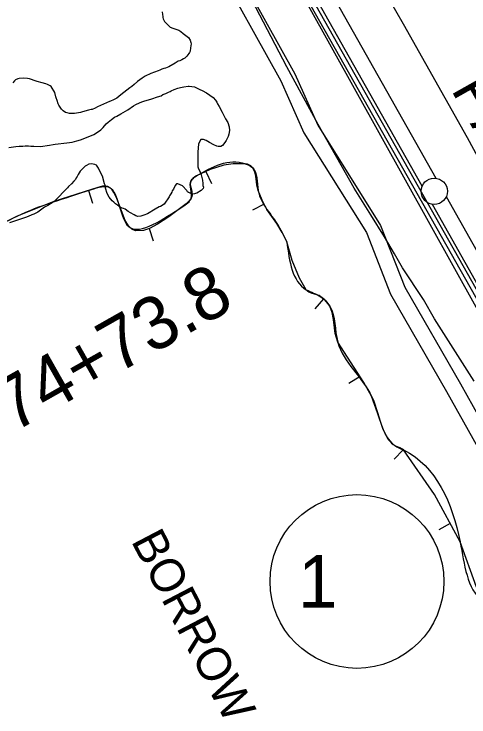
# Model space of a CAD drawing. Extents: x 3177185 to 3215018, y 812988 to 838321.
# Drawn here: x 3194496 to 3195360, y 819225 to 820560 of the extents above; entities that cross this region are included whole.
import ezdxf

# ---------------------------------------------------------------- set-up
doc = ezdxf.new("R2010")
doc.units = 0
for name, color, linetype in [('V-BORW-IDEN', 7, 'Continuous'), ('V-BORW-LINE', 7, 'Continuous'), ('V-LEVE-TOET', 7, 'Continuous'), ('V-RAIL-IDEN', 7, 'Continuous'), ('V-RAIL-TRAK', 7, 'Continuous'), ('V-ROAD-CNTR', 7, 'Continuous'), ('V-ROAD-IDEN', 7, 'Continuous'), ('V-SITE-VEGE', 7, 'Continuous'), ('V-SURV-IDEN', 7, 'Continuous'), ('V-SURV-LINE', 7, 'Continuous'), ('V-TOPO-SHOR', 7, 'Continuous')]:
    doc.layers.add(name, color=color, linetype=linetype)

msp = doc.modelspace()

# ---------------------------------------------------------------- linework, layer by layer
at = {"layer": 'V-BORW-LINE'}
for p, q in [((3194860.5, 820261), (3194871.3, 820238.4)), ((3194638, 820224.9), (3194645.6, 820201)), ((3194971.4, 820199.1), (3194949.2, 820187.8)), ((3194752.8, 820152.8), (3194760.8, 820129.1)), ((3195083.7, 820019.3), (3195067.6, 820000.2)), ((3195153.2, 819871.8), (3195132.2, 819858.2)), ((3195235.4, 819732.7), (3195218.3, 819714.5)), ((3195324.6, 819592.3), (3195302.5, 819580.5))]:
    msp.add_line(p, q, dxfattribs=at)
for points in [[(3195014.2, 820127.7), (3195005.1, 820145.4), (3194995.1, 820162.4), (3194985.8, 820175.7), (3194976.6, 820189), (3194967.6, 820206.7), (3194960, 820224.8), (3194957.2, 820235.5), (3194955.3, 820252.1), (3194953.2, 820260.4), (3194949, 820268.4), (3194946.1, 820271.5), (3194943.6, 820273.3), (3194939.5, 820275), (3194935.3, 820275.8), (3194912.4, 820275.7), (3194894.9, 820273), (3194868.7, 820264.9), (3194842.9, 820252.6), (3194839.8, 820250.7), (3194835.9, 820247.5), (3194832.6, 820243.6), (3194831.1, 820239.8), (3194830.8, 820236.2), (3194833.7, 820222.8), (3194834.5, 820216.3), (3194834.1, 820213.3), (3194832.8, 820210.5), (3194829.2, 820205.8), (3194822.9, 820199.6), (3194815.7, 820194), (3194790.2, 820175), (3194769, 820161), (3194753.3, 820153), (3194742.1, 820149.2), (3194726.9, 820148.6), (3194720.3, 820151.2), (3194714.7, 820155.9), (3194707.3, 820167.7), (3194691.3, 820209.9), (3194686.1, 820220.8), (3194682.9, 820225.9), (3194678.6, 820230.1), (3194674.6, 820232.2), (3194670.9, 820233.1), (3194664, 820233), (3194653.5, 820230.2), (3194643.3, 820226.6), (3194572.1, 820203.9), (3194502.5, 820176.3), (3194474.3, 820162.1)], [(3195051.2, 820036.5), (3195038.2, 820058.1), (3195024.1, 820092.2), (3195014.2, 820127.7)], [(3195374.2, 819471.5), (3195343.1, 819557.8), (3195294.7, 819647.9), (3195236, 819732.1), (3195234, 819733.9), (3195229.7, 819736.2), (3195222.6, 819738.7), (3195219.2, 819740.3), (3195216.4, 819742.6), (3195205.6, 819756), (3195201, 819763.3), (3195197, 819771), (3195186.1, 819802.7), (3195175.2, 819834.1), (3195160.5, 819860.5), (3195110.9, 819937.1), (3195105.8, 819953.5), (3195102.9, 819980), (3195100.5, 819993.1), (3195095.7, 820005.5), (3195092.3, 820010.6), (3195086.1, 820017.2), (3195079.1, 820023.1), (3195075.8, 820025.2), (3195062.5, 820029.5), (3195056.2, 820032), (3195053.5, 820033.9), (3195051.2, 820036.5)]]:
    msp.add_lwpolyline(points, dxfattribs=at)
for points in [[(3194584.7, 819145.8), (3194447.3, 819133.8), (3194404.6, 819199.8), (3194370.1, 819313.4), (3194215, 819487.3), (3194145.9, 819581.9), (3194097.2, 819676.7), (3194042.5, 819943.4), (3194160.3, 819974.7), (3194208.8, 820009.4), (3194249.9, 820024.5), (3194281, 820046.5), (3194446.7, 820147), (3194502.5, 820176.3), (3194643.3, 820226.6), (3194678.6, 820230.1), (3194691.3, 820209.9), (3194714.7, 820155.9), (3194815.7, 820194), (3194832.8, 820210.5), (3194832.6, 820243.6), (3194842.9, 820252.6), (3194935.3, 820275.8), (3194949, 820268.4), (3194960, 820224.8), (3194976.6, 820189), (3194995.1, 820162.4), (3195014.2, 820127.7)], [(3195014.2, 820127.7), (3195051.2, 820036.5), (3195079.1, 820023.1), (3195095.7, 820005.5), (3195110.9, 819937.1), (3195175.2, 819834.1), (3195197, 819771), (3195216.4, 819742.6), (3195236, 819732.1), (3195343.1, 819557.8), (3195386.4, 819443.9), (3195423.7, 819413.9), (3195435.2, 819377.3), (3195508.3, 819247.2), (3195522.8, 819188.1), (3195531.4, 819165.4), (3195561.3, 819137), (3195612, 819024.1), (3195671.6, 818940.9), (3195804.7, 818724.1), (3195856.6, 818587.8), (3195891.3, 818540.3), (3195947, 818433), (3195956.5, 818375.3), (3195958.6, 818365.3)]]:
    msp.add_spline(points, degree=3, dxfattribs=at)
at = {"layer": 'V-LEVE-TOET'}
for points in [[(3195369.9, 819862.9), (3195294.5, 819981.2), (3195273.4, 820017.6), (3195233.7, 820077.8), (3195218.6, 820104.8), (3195199.4, 820136.6), (3195173.6, 820178.4), (3195142.1, 820229.4), (3195073.8, 820350.4), (3195014.1, 820460), (3194933, 820615.4), (3194826.9, 820807.9), (3194726, 820985.8), (3194603, 821208.6), (3194474, 821433.9), (3194336.7, 821672), (3194255.3, 821803.4)], [(3195368.6, 820787.1), (3195357.2, 820770.6), (3195346.6, 820754.6), (3195334.3, 820739.9), (3195319.5, 820726.5), (3195306.2, 820715.4), (3195290.9, 820704.8), (3195270.3, 820693.3), (3195230.7, 820666.8), (3195213.6, 820660.8), (3195195.1, 820654), (3195186.1, 820650.5), (3195181.3, 820645.8), (3195179.2, 820635.1), (3195181.5, 820629), (3195191.4, 820611.7), (3195205.7, 820592.5), (3195235, 820541.5), (3195356.3, 820325.5), (3195489.6, 820080.5)]]:
    msp.add_lwpolyline(points, dxfattribs=at)
at = {"layer": 'V-RAIL-TRAK'}
msp.add_lwpolyline([(3194238.4, 822033.7), (3194389.3, 821767.4), (3194710.7, 821197.3), (3195003.1, 820677), (3195353.4, 820056.4), (3195586, 819645), (3195933.8, 819028.7), (3196235.6, 818491.2), (3196308.1, 818364.4)], dxfattribs=at)
at = {"layer": 'V-ROAD-CNTR'}
for points in [[(3193546.7, 823116.4), (3193719.6, 822803.7), (3193783.2, 822690.8), (3193839.5, 822561.1), (3193931.2, 822385.2), (3194075.1, 822116.1), (3194127.2, 822033.7), (3194185.2, 821977.8), (3194639.7, 821147.1), (3195029.5, 820446.4), (3195072.9, 820348.7), (3195192.1, 820158.7), (3195238.4, 820041.1), (3195343.7, 819857.8), (3195584.5, 819427.5), (3195690.6, 819249.8), (3195813.3, 819032.3), (3196001.4, 818698.6), (3196174.6, 818374.5)], [(3193520.4, 823101.8), (3193693.4, 822789.1), (3193756.3, 822677.4), (3193812.4, 822548.2), (3193904.7, 822371.2), (3194049.2, 822101), (3194103.8, 822014.6), (3194161.1, 821959.4), (3194613.5, 821132.6), (3195002.6, 820433), (3195046.3, 820334.6), (3195165.2, 820145.1), (3195211.3, 820028), (3195317.6, 819843), (3195558.5, 819412.5), (3195664.6, 819234.7), (3195787.2, 819017.6), (3195975.1, 818684.1), (3196148.1, 818360.4)], [(3193654.2, 823085.5), (3194393.6, 821781.9), (3194932.5, 820818.5), (3195643.8, 819559.4), (3196039.6, 818863.6), (3196103.7, 818747.1), (3196200.1, 818577.4), (3196283.3, 818430.9), (3196319.7, 818367.1)]]:
    msp.add_lwpolyline(points, dxfattribs=at)
at = {"layer": 'V-ROAD-IDEN'}
msp.add_circle((3195147.4, 819482.4), 165, dxfattribs=at)
at = {"layer": 'V-SITE-VEGE'}
for p, q in [((3194777.6, 820564.2), (3194778.5, 820559.3)), ((3194778.5, 820559.3), (3194778.9, 820555.3)), ((3194778.9, 820555.3), (3194778.9, 820553.3)), ((3194778.9, 820553.3), (3194779.4, 820550.9)), ((3194779.4, 820550.9), (3194781.8, 820545.6)), ((3194781.8, 820545.6), (3194792.9, 820534.8)), ((3194792.9, 820534.8), (3194798.1, 820532.9)), ((3194798.1, 820532.9), (3194801.8, 820532.1)), ((3194801.8, 820532.1), (3194809.1, 820529.3)), ((3194809.1, 820529.3), (3194813.1, 820526.9)), ((3194813.1, 820526.9), (3194817.2, 820523.3)), ((3194817.2, 820523.3), (3194827.4, 820515.7)), ((3194827.4, 820515.7), (3194830.7, 820510.5)), ((3194830.7, 820510.5), (3194832.3, 820506.1)), ((3194832.4, 820503.7), (3194831.6, 820495.6)), ((3194832.3, 820506.1), (3194832.4, 820503.7)), ((3194829.7, 820486.7), (3194828.1, 820485)), ((3194830.5, 820489.5), (3194829.7, 820486.7)), ((3194831.6, 820495.6), (3194830.5, 820489.5)), ((3194814.9, 820473.2), (3194811.2, 820471.1)), ((3194818.1, 820474.8), (3194814.9, 820473.2)), ((3194820.9, 820476.5), (3194818.1, 820474.8)), ((3194824.1, 820479.7), (3194820.9, 820476.5)), ((3194828.1, 820485), (3194824.1, 820479.7)), ((3194790.3, 820460), (3194783.9, 820457.1)), ((3194802.4, 820467), (3194790.3, 820460)), ((3194808, 820470.3), (3194802.4, 820467)), ((3194811.2, 820471.1), (3194808, 820470.3)), ((3194756.1, 820447.2), (3194745.6, 820442.2)), ((3194769.8, 820452.1), (3194756.1, 820447.2)), ((3194773.4, 820453.4), (3194769.8, 820452.1)), ((3194777, 820455), (3194773.4, 820453.4)), ((3194780.7, 820456.3), (3194777, 820455)), ((3194783.9, 820457.1), (3194780.7, 820456.3)), ((3194497.5, 820433), (3194493.9, 820429.3)), ((3194499.1, 820435), (3194497.5, 820433)), ((3194503.5, 820437.1), (3194499.1, 820435)), ((3194506.3, 820437.9), (3194503.5, 820437.1)), ((3194514, 820438), (3194506.3, 820437.9)), ((3194522.1, 820437.7), (3194514, 820438)), ((3194525.8, 820436.9), (3194522.1, 820437.7)), ((3194529.8, 820435.7), (3194525.8, 820436.9)), ((3194534.3, 820434.1), (3194529.8, 820435.7)), ((3194540.4, 820431.8), (3194534.3, 820434.1)), ((3194739.6, 820438.5), (3194730.8, 820432)), ((3194745.6, 820442.2), (3194739.6, 820438.5)), ((3194549.7, 820429.4), (3194540.4, 820431.8)), ((3194556.6, 820427.5), (3194549.7, 820429.4)), ((3194560.2, 820426.3), (3194556.6, 820427.5)), ((3194565.1, 820423.9), (3194560.2, 820426.3)), ((3194566.7, 820422.7), (3194565.1, 820423.9)), ((3194573.7, 820411.1), (3194566.7, 820422.7)), ((3194716.3, 820420.1), (3194699.1, 820406.6)), ((3194719.9, 820422.6), (3194716.3, 820420.1)), ((3194724.3, 820426.2), (3194719.9, 820422.6)), ((3194730.8, 820432), (3194724.3, 820426.2)), ((3194800.4, 820416.9), (3194807.3, 820419.3)), ((3194807.3, 820419.3), (3194812.5, 820420.6)), ((3194812.5, 820420.6), (3194818.6, 820421.9)), ((3194818.6, 820421.9), (3194827.1, 820422.8)), ((3194827.1, 820422.8), (3194829.1, 820423.2)), ((3194829.1, 820423.2), (3194838.8, 820421.7)), ((3194838.8, 820421.7), (3194849.4, 820416.9)), ((3194575.8, 820402.6), (3194573.7, 820411.1)), ((3194699.1, 820406.6), (3194691.4, 820400.5)), ((3194775.5, 820404.9), (3194778.7, 820406.9)), ((3194778.7, 820406.9), (3194784.3, 820409)), ((3194784.3, 820409), (3194789.6, 820411.5)), ((3194789.6, 820411.5), (3194792.8, 820413.1)), ((3194792.8, 820413.1), (3194794.8, 820414)), ((3194794.8, 820414), (3194800.4, 820416.9)), ((3194849.4, 820416.9), (3194853.8, 820414.9)), ((3194853.8, 820414.9), (3194861.9, 820410.6)), ((3194861.9, 820410.6), (3194874.2, 820401.4)), ((3194576.2, 820400.6), (3194575.8, 820402.6)), ((3194578.3, 820395.8), (3194576.2, 820400.6)), ((3194580.4, 820389.7), (3194578.3, 820395.8)), ((3194677.8, 820393.9), (3194666.1, 820388.9)), ((3194679.8, 820394.3), (3194677.8, 820393.9)), ((3194685.4, 820396.8), (3194679.8, 820394.3)), ((3194691.4, 820400.5), (3194685.4, 820396.8)), ((3194734.8, 820391.6), (3194738.8, 820393.2)), ((3194738.8, 820393.2), (3194742.8, 820394.5)), ((3194742.8, 820394.5), (3194757.8, 820398.7)), ((3194757.8, 820398.7), (3194768.6, 820402.8)), ((3194768.6, 820402.8), (3194775.5, 820404.9)), ((3194874.2, 820401.4), (3194879.1, 820396.2)), ((3194879.1, 820396.2), (3194881.1, 820392.6)), ((3194881.1, 820392.6), (3194882.4, 820389.3)), ((3194581.2, 820386.9), (3194580.4, 820389.7)), ((3194586.5, 820379.3), (3194581.2, 820386.9)), ((3194589.4, 820376.5), (3194586.5, 820379.3)), ((3194650.4, 820381.1), (3194644.8, 820378.6)), ((3194654.8, 820383.5), (3194650.4, 820381.1)), ((3194666.1, 820388.9), (3194654.8, 820383.5)), ((3194712.3, 820378), (3194723.1, 820385.4)), ((3194723.1, 820385.4), (3194727.9, 820387.9)), ((3194727.9, 820387.9), (3194734.8, 820391.6)), ((3194882.4, 820389.3), (3194886, 820384.5)), ((3194886, 820384.5), (3194891.4, 820373.6)), ((3194594.3, 820373.3), (3194589.4, 820376.5)), ((3194597.1, 820372.1), (3194594.3, 820373.3)), ((3194601.6, 820371.3), (3194597.1, 820372.1)), ((3194610.9, 820371.4), (3194601.6, 820371.3)), ((3194622.6, 820373.1), (3194610.9, 820371.4)), ((3194626.6, 820374.4), (3194622.6, 820373.1)), ((3194637.9, 820377.3), (3194626.6, 820374.4)), ((3194642.7, 820378.6), (3194637.9, 820377.3)), ((3194644.8, 820378.6), (3194642.7, 820378.6)), ((3194687.3, 820364), (3194691.8, 820366.1)), ((3194691.8, 820366.1), (3194699, 820370.2)), ((3194699, 820370.2), (3194712.3, 820378)), ((3194891.4, 820373.6), (3194898, 820361.2)), ((3194671.3, 820351.4), (3194674.9, 820354.6)), ((3194674.9, 820354.6), (3194681.7, 820359.9)), ((3194681.7, 820359.9), (3194687.3, 820364)), ((3194898, 820361.2), (3194902.1, 820354.3)), ((3194902.1, 820354.3), (3194905, 820345.9)), ((3194656.9, 820337.1), (3194660.9, 820339.9)), ((3194660.9, 820339.9), (3194665.7, 820344.4)), ((3194665.7, 820344.4), (3194671.3, 820351.4)), ((3194905.1, 820339), (3194904.3, 820332.1)), ((3194905, 820345.9), (3194905.1, 820339)), ((3194630.7, 820324.3), (3194647.6, 820331.3)), ((3194647.6, 820331.3), (3194656.9, 820337.1)), ((3194902.8, 820327.7), (3194899.2, 820320)), ((3194904.3, 820332.1), (3194902.8, 820327.7)), ((3194563.7, 820310.7), (3194570.6, 820312)), ((3194570.6, 820312), (3194574.2, 820312.8)), ((3194574.2, 820312.8), (3194596.8, 820315.1)), ((3194596.8, 820315.1), (3194606.5, 820316.8)), ((3194606.5, 820316.8), (3194615.8, 820319.3)), ((3194615.8, 820319.3), (3194622.3, 820321.4)), ((3194622.3, 820321.4), (3194630.7, 820324.3)), ((3194846.7, 820313.8), (3194845.2, 820297.6)), ((3194850.7, 820321.9), (3194846.7, 820313.8)), ((3194856.3, 820322), (3194850.7, 820321.9)), ((3194861.2, 820320), (3194856.3, 820322)), ((3194867.3, 820316), (3194861.2, 820320)), ((3194875.8, 820311.6), (3194867.3, 820316)), ((3194896.8, 820315.9), (3194892.4, 820310.6)), ((3194899.2, 820320), (3194896.8, 820315.9)), ((3194486.2, 820306.3), (3194499.5, 820308.5)), ((3194499.5, 820308.5), (3194506.3, 820309)), ((3194506.3, 820309), (3194513.2, 820309)), ((3194513.2, 820309), (3194517.7, 820309.5)), ((3194517.7, 820309.5), (3194523.7, 820309.5)), ((3194523.7, 820309.5), (3194528.2, 820308.8)), ((3194528.2, 820308.8), (3194533.8, 820308.8)), ((3194533.8, 820308.8), (3194546.8, 820308.5)), ((3194546.8, 820308.5), (3194563.7, 820310.7)), ((3194881.1, 820309.3), (3194875.8, 820311.6)), ((3194883.9, 820308.5), (3194881.1, 820309.3)), ((3194889.2, 820308.5), (3194883.9, 820308.5)), ((3194892.4, 820310.6), (3194889.2, 820308.5)), ((3194845.2, 820297.6), (3194845.4, 820281.8)), ((3194634, 820272.6), (3194631.6, 820270.9)), ((3194638.1, 820274.6), (3194634, 820272.6)), ((3194643.3, 820275.5), (3194638.1, 820274.6)), ((3194649.8, 820274.3), (3194643.3, 820275.5)), ((3194653, 820272.8), (3194649.8, 820274.3)), ((3194656.7, 820267.5), (3194653, 820272.8)), ((3194845.4, 820281.8), (3194845, 820279.4)), ((3194845, 820279.4), (3194845.5, 820269.7)), ((3194622, 820261.5), (3194618, 820255.4)), ((3194627.2, 820266.9), (3194622, 820261.5)), ((3194629.2, 820268.9), (3194627.2, 820266.9)), ((3194631.6, 820270.9), (3194629.2, 820268.9)), ((3194658.8, 820262.7), (3194656.7, 820267.5)), ((3194664.1, 820252.2), (3194658.8, 820262.7)), ((3194845.5, 820269.7), (3194846.3, 820266.1)), ((3194846.3, 820266.1), (3194848.8, 820261.3)), ((3194848.8, 820261.3), (3194851.7, 820254.4)), ((3194612.9, 820246.1), (3194610.1, 820242.8)), ((3194614.4, 820248.9), (3194612.9, 820246.1)), ((3194616, 820251.4), (3194614.4, 820248.9)), ((3194618, 820255.4), (3194616, 820251.4)), ((3194667.9, 820237.7), (3194664.1, 820252.2)), ((3194851.7, 820254.4), (3194854.2, 820244.7)), ((3194599.6, 820232.2), (3194597.7, 820229.8)), ((3194605.3, 820237.5), (3194599.6, 820232.2)), ((3194610.1, 820242.8), (3194605.3, 820237.5)), ((3194669.2, 820234.9), (3194667.9, 820237.7)), ((3194670, 820229.3), (3194669.2, 820234.9)), ((3194802.2, 820234.5), (3194799, 820227.6)), ((3194804.6, 820237.4), (3194802.2, 820234.5)), ((3194807.4, 820237.4), (3194804.6, 820237.4)), ((3194815.9, 820233.5), (3194807.4, 820237.4)), ((3194824.1, 820225.1), (3194815.9, 820233.5)), ((3194854.2, 820244.7), (3194855.1, 820238.3)), ((3194855.1, 820238.3), (3194855.1, 820234.6)), ((3194855.1, 820234.6), (3194856, 820231.4)), ((3194591.6, 820223.7), (3194580.4, 820211.8)), ((3194597.7, 820229.8), (3194591.6, 820223.7)), ((3194673.3, 820219.2), (3194670, 820229.3)), ((3194677.1, 820212.3), (3194673.3, 820219.2)), ((3194795.8, 820222), (3194793.8, 820218.3)), ((3194796.6, 820224), (3194795.8, 820222)), ((3194799, 820227.6), (3194796.6, 820224)), ((3194825.7, 820222.6), (3194824.1, 820225.1)), ((3194827.4, 820221.4), (3194825.7, 820222.6)), ((3194829.4, 820220.3), (3194827.4, 820221.4)), ((3194832.2, 820219.1), (3194829.4, 820220.3)), ((3194836.3, 820217.9), (3194832.2, 820219.1)), ((3194843.1, 820219.6), (3194836.3, 820217.9)), ((3194851.6, 820224.9), (3194843.1, 820219.6)), ((3194855.6, 820229), (3194851.6, 820224.9)), ((3194856, 820231.4), (3194855.6, 820229)), ((3194576.4, 820207.8), (3194570.4, 820202.8)), ((3194580.4, 820211.8), (3194576.4, 820207.8)), ((3194682.8, 820205.5), (3194677.1, 820212.3)), ((3194686, 820202.7), (3194682.8, 820205.5)), ((3194791, 820213), (3194781.1, 820198.8)), ((3194791.8, 820215), (3194791, 820213)), ((3194793.8, 820218.3), (3194791.8, 820215)), ((3194553.9, 820193), (3194541.5, 820184)), ((3194560.4, 820196.7), (3194553.9, 820193)), ((3194570.4, 820202.8), (3194560.4, 820196.7)), ((3194688.9, 820199.5), (3194686, 820202.7)), ((3194693, 820197.1), (3194688.9, 820199.5)), ((3194695.8, 820194.7), (3194693, 820197.1)), ((3194701.9, 820191.1), (3194695.8, 820194.7)), ((3194772.2, 820193.8), (3194764.2, 820189.3)), ((3194774.2, 820194.7), (3194772.2, 820193.8)), ((3194781.1, 820198.8), (3194774.2, 820194.7)), ((3194530.2, 820178.6), (3194523.4, 820175.7)), ((3194533.8, 820179.9), (3194530.2, 820178.6)), ((3194537.5, 820181.9), (3194533.8, 820179.9)), ((3194541.5, 820184), (3194537.5, 820181.9)), ((3194703.9, 820190.4), (3194701.9, 820191.1)), ((3194707.6, 820189.2), (3194703.9, 820190.4)), ((3194713.3, 820185.2), (3194707.6, 820189.2)), ((3194717.4, 820182.8), (3194713.3, 820185.2)), ((3194724.3, 820178.4), (3194717.4, 820182.8)), ((3194727.5, 820176.8), (3194724.3, 820178.4)), ((3194749.7, 820180.7), (3194742.5, 820177.8)), ((3194764.2, 820189.3), (3194749.7, 820180.7)), ((3194518.1, 820173.6), (3194487.9, 820163.3)), ((3194523.4, 820175.7), (3194518.1, 820173.6)), ((3194731.2, 820175.7), (3194727.5, 820176.8)), ((3194736.8, 820176.1), (3194731.2, 820175.7)), ((3194742.5, 820177.8), (3194736.8, 820176.1))]:
    msp.add_line(p, q, dxfattribs=at)
at = {"layer": 'V-SURV-LINE'}
for points in [[(3194010.9, 822526.1), (3195297.4, 820248.2)], [(3195271.3, 820233.4), (3193984.8, 822511.3)], [(3195317, 820213.3), (3196292.2, 818481.1)], [(3196266.1, 818466.4), (3195290.9, 820198.6)]]:
    msp.add_lwpolyline(points, dxfattribs=at)
msp.add_circle((3195294.2, 820223.4), 25, dxfattribs=at)
at = {"layer": 'V-TOPO-SHOR'}
msp.add_lwpolyline([(3195564, 819660.7), (3195052.1, 820581.1), (3194839.3, 820937.7), (3194281, 821921.4), (3194057, 822347), (3193780.9, 822818.6), (3193257.4, 823744.7), (3192803, 824538.5), (3192509.7, 825084.9), (3192365.9, 825332.3), (3191974.7, 826039.8)], dxfattribs=at)

# ---------------------------------------------------------------- texts
at = {"layer": 'V-BORW-IDEN'}
msp.add_text('BORROW', height=64, rotation=297.592, dxfattribs=at).set_placement((3194717.7, 819559.5))
at = {"layer": 'V-RAIL-IDEN'}
msp.add_text('PACIFIC', height=83, rotation=299.3872, dxfattribs=at).set_placement((3195325, 820416.8))
at = {"layer": 'V-ROAD-IDEN'}
msp.add_text(' 1 ', height=100, dxfattribs=at).set_placement((3194998.5, 819432.4))
at = {"layer": 'V-SURV-IDEN'}
msp.add_text('1374+73.8', height=100, rotation=29.5144, dxfattribs=at).set_placement((3194365.1, 819690.8))

doc.saveas('drawing.dxf')
